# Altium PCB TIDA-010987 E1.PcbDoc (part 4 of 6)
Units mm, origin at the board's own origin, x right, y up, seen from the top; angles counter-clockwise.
Board outline 154.15 x 103.76 mm, 4 copper layers (5V, GND, MidSupply, -5V), stack 1.787 mm thick; 92 components, 52 nets, 1640 pads, 56 vias.
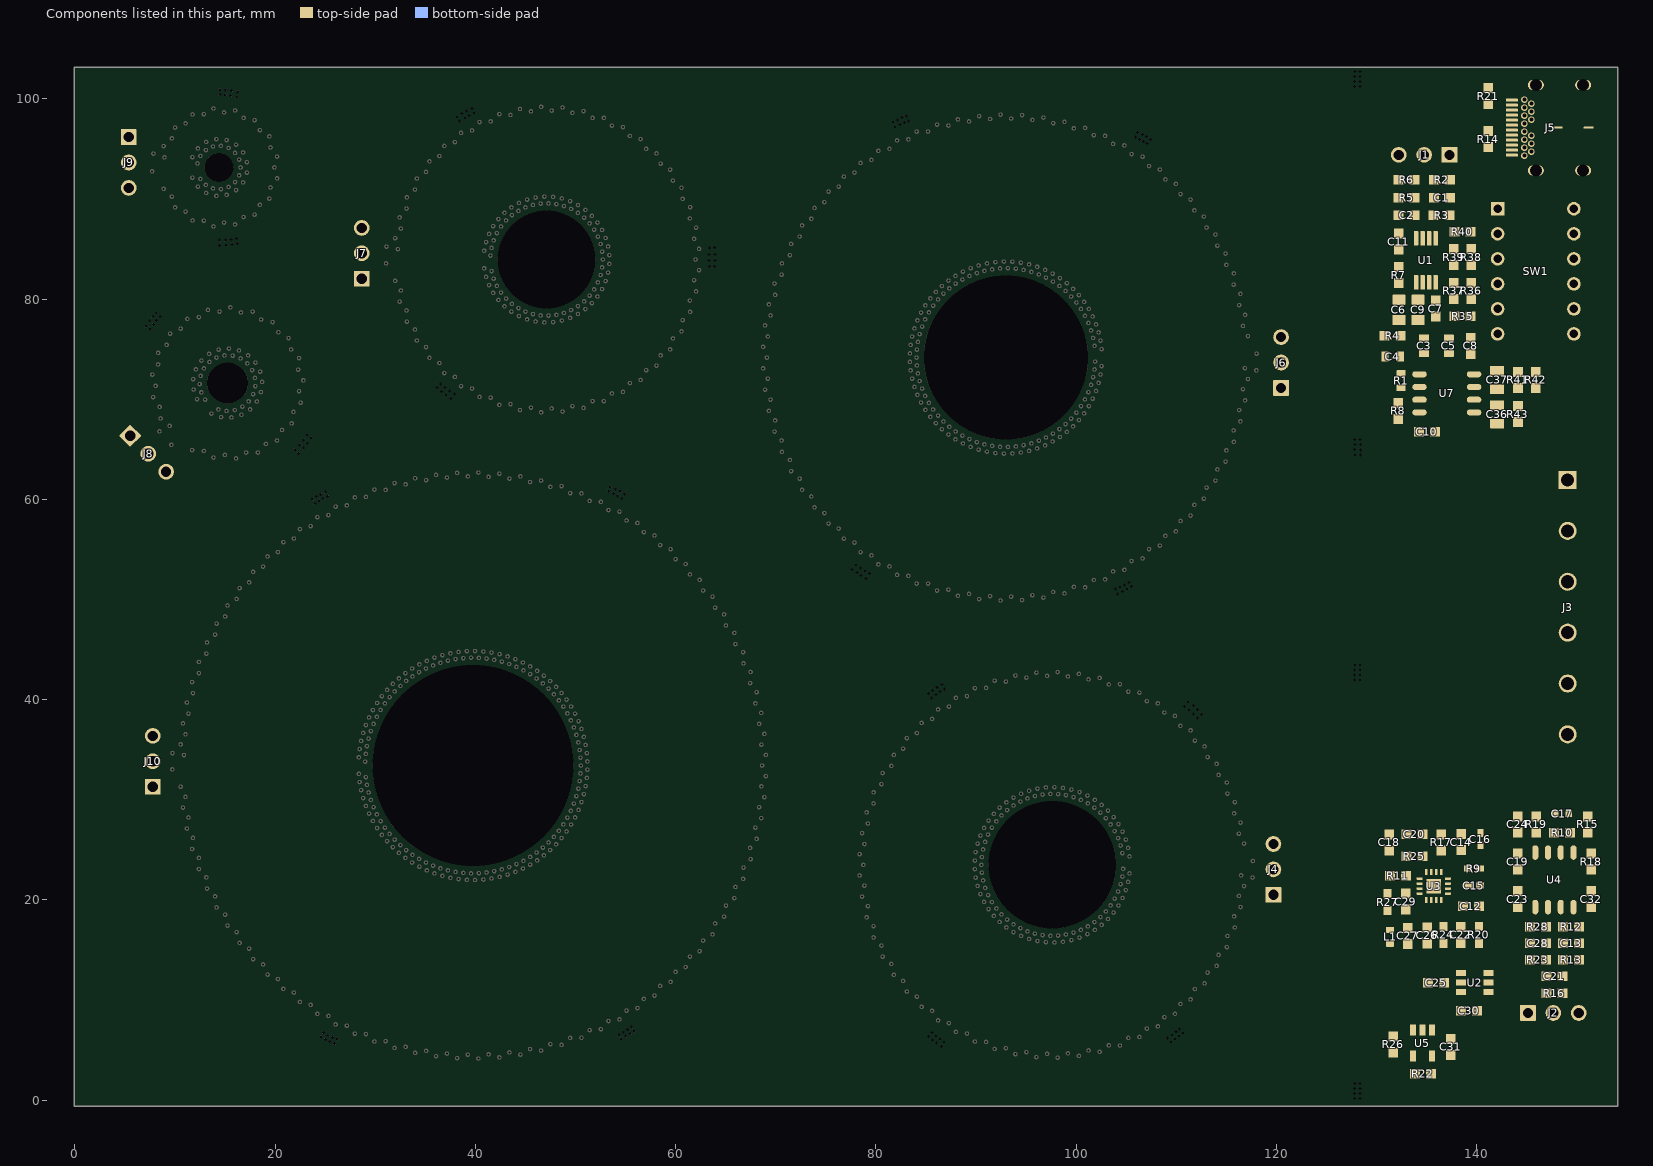
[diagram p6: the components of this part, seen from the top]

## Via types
v1: diameter 0.61, hole 0.203, 5V to -5V, tented both sides, 52 vias
v2: diameter 0.5, hole 0.2, 5V to -5V, tented both sides, 4 vias

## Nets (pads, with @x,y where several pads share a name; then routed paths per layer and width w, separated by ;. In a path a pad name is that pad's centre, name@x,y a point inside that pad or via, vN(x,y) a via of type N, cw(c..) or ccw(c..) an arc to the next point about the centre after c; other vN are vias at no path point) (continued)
copper on no net: (continued)
  5V w0.1: 97.842,31.244 98.148,42.365 ccw(c98.159,42.75) 98.544,42.736 cw(c97.628,23.493) 99.892,42.624 cw(c100.274,42.575) 100.655,42.518 cw(c97.628,23.493) 102.357,42.168 ; 98.213,16.43 99.187,4.677 ; 98.213,30.556 99.187,42.308 ; 98.339,67.001 ccw(c92.996,74.152) 98.657,67.251 cw(c98.95,67.501) 99.231,67.764 ccw(c92.996,74.152) 99.245,67.778 ccw(c99.514,68.053) 99.795,67.79 110.433,57.836 ; 98.339,81.304 ccw(c92.996,74.152) 98.009,81.539 cw(c97.686,81.748) 97.354,81.943 ccw(c92.996,74.152) 97.336,81.953 ccw(c96.996,82.133) 97.169,82.477 103.696,95.501 ; 98.392,66.22 106.428,54.408 ccw(c106.644,54.089) 106.324,53.875 cw(c92.996,74.152) 105.152,53.152 cw(c104.818,52.962) 104.48,52.777 cw(c92.996,74.152) 102.898,52 ; 98.392,82.085 106.644,94.216 ; 98.693,31.173 100.274,42.575 ; 98.95,67.501 108.923,56.359 ; 98.95,80.804 108.923,91.946 ; 98.987,16.537 ccw(c97.628,23.493) 99.373,16.624 cw(c99.744,16.729) 100.108,16.853 ccw(c97.628,23.493) 100.119,16.857 ccw(c100.475,17.002) 100.63,16.65 105.212,6.203 ; 99.072,66.728 108.364,55.374 ; 99.072,81.577 108.12,92.633 ccw(c108.364,92.931) 108.66,92.685 cw(c92.996,74.152) 109.686,91.766 cw(c109.963,91.499) 110.237,91.228 cw(c92.996,74.152) 111.43,89.932 ; 99.514,68.053 ccw(c92.996,74.152) 99.784,68.355 cw(c100.028,68.653) 100.258,68.962 ccw(c92.996,74.152) 100.27,68.978 ccw(c100.486,69.296) 100.809,69.087 113.033,61.161 ; 99.514,80.252 ccw(c92.996,74.152) 99.231,80.541 cw(c98.95,80.804) 98.657,81.054 ccw(c92.996,74.152) 98.642,81.067 ccw(c98.339,81.304) 98.569,81.612 107.288,93.284 ; 99.532,15.976 102.357,4.817 ; 99.532,31.009 102.263,41.795 ccw(c102.357,42.168) 102.73,42.07 cw(c97.628,23.493) 104.021,41.666 cw(c104.383,41.535) 104.742,41.396 cw(c97.628,23.493) 106.327,40.682 ; 99.704,67.294 109.694,57.081 ccw(c109.963,56.806) 109.686,56.539 cw(c92.996,74.152) 108.66,55.62 cw(c108.364,55.374) 108.064,55.133 cw(c92.996,74.152) 106.644,54.089 ; 99.704,81.011 109.963,91.499 ; 99.744,16.729 103.264,5.473 ; 99.744,30.257 103.264,41.512 ; 100.028,68.653 111.807,59.441 ; 100.028,79.652 111.807,88.864 ; 100.274,4.41 ccw(c97.628,23.493) 101.983,4.726 ccw(c102.357,4.817) 102.73,4.915 ccw(c97.628,23.493) 104.021,5.319 cw(c104.383,5.451) 104.248,5.811 100.347,16.231 ; 100.284,67.914 111.43,58.373 ; 100.284,80.391 111.138,89.681 ccw(c111.43,89.932) 111.678,89.637 cw(c92.996,74.152) 112.527,88.552 cw(c112.753,88.241) 112.974,87.926 cw(c92.996,74.152) 113.92,86.44 ; 100.347,30.754 104.383,41.535 ; 100.475,17.002 ccw(c97.628,23.493) 100.833,17.172 cw(c101.172,17.355) 101.5,17.556 ccw(c97.628,23.493) 101.509,17.563 ccw(c101.826,17.782) 102.053,17.472 108.81,8.28 ; 100.475,29.983 ccw(c97.628,23.493) 100.108,30.132 cw(c99.744,30.257) 99.373,30.362 ccw(c97.628,23.493) 99.363,30.364 ccw(c98.987,30.448) 99.061,30.826 101.248,42.022 ; 100.486,69.296 ccw(c92.996,74.152) 100.699,69.641 cw(c100.886,69.977) 101.059,70.321 ccw(c92.996,74.152) 101.068,70.339 ccw(c101.224,70.691) 101.579,70.542 115.008,64.892 ; 100.486,79.009 ccw(c92.996,74.152) 100.258,79.343 cw(c100.028,79.652) 99.784,79.95 ccw(c92.996,74.152) 99.771,79.965 ccw(c99.514,80.252) 99.795,80.515 110.433,90.469 ; 100.807,68.583 112.439,60.288 ccw(c112.753,60.064) 112.527,59.752 cw(c92.996,74.152) 111.678,58.668 cw(c111.43,58.373) 111.177,58.083 cw(c92.996,74.152) 109.963,56.806 ; 100.807,79.722 112.753,88.241 ; 100.886,69.977 114.103,62.983 ; 100.886,78.328 114.103,85.322 ; 101.129,16.574 106.327,6.303 ; 101.129,30.411 106.153,40.338 ccw(c106.327,40.682) 106.669,40.505 cw(c97.628,23.493) 107.841,39.828 cw(c108.165,39.621) 108.485,39.407 cw(c97.628,23.493) 109.875,38.364 ; 101.172,17.355 107.068,7.142 ; 101.172,29.63 107.068,39.843 ; 101.224,70.691 ccw(c92.996,74.152) 101.373,71.068 cw(c101.498,71.432) 101.608,71.801 ccw(c92.996,74.152) 101.613,71.82 ccw(c101.705,72.194) 102.081,72.109 116.294,68.912 ; 101.224,77.614 ccw(c92.996,74.152) 101.059,77.984 cw(c100.886,78.328) 100.699,78.664 ccw(c92.996,74.152) 100.689,78.681 ccw(c100.486,79.009) 100.809,79.218 113.033,87.144 ; 101.269,69.295 113.92,61.865 ; 101.269,79.01 113.588,86.245 ccw(c113.92,86.44) 114.113,86.106 cw(c92.996,74.152) 114.757,84.889 cw(c114.924,84.542) 115.087,84.193 cw(c92.996,74.152) 115.757,82.564 ; 101.498,71.432 115.74,66.874 ; 101.498,76.873 115.74,81.431 ; 101.666,70.045 114.577,63.928 ccw(c114.924,63.763) 114.757,63.416 cw(c92.996,74.152) 114.113,62.199 cw(c113.92,61.865) 113.723,61.535 cw(c92.996,74.152) 112.753,60.064 ; 101.666,78.26 114.924,84.542 ; 101.705,72.194 ccw(c92.996,74.152) 101.785,72.591 cw(c101.844,72.971) 101.887,73.354 ccw(c92.996,74.152) 101.889,73.373 ccw(c101.914,73.758) 102.299,73.741 116.853,73.096 ; 101.705,76.111 ccw(c92.996,74.152) 101.608,76.504 cw(c101.498,76.873) 101.373,77.237 ccw(c92.996,74.152) 101.366,77.256 ccw(c101.224,77.614) 101.579,77.763 115.008,83.413 ; 101.826,17.782 ccw(c97.628,23.493) 102.138,18.025 cw(c102.428,18.278) 102.704,18.547 ccw(c97.628,23.493) 102.712,18.555 ccw(c102.973,18.838) 103.263,18.585 111.866,11.093 ; 101.826,29.203 ccw(c97.628,23.493) 101.5,29.429 cw(c101.172,29.63) 100.833,29.814 ccw(c97.628,23.493) 100.823,29.819 ccw(c100.475,29.983) 100.63,30.335 105.212,40.782 ; 101.844,72.971 116.666,70.992 ; 101.844,75.334 116.666,77.313 ; 101.869,17.001 107.955,7.687 ccw(c108.165,7.365) 107.841,7.157 cw(c97.628,23.493) 106.669,6.481 cw(c106.327,6.303) 105.982,6.133 cw(c97.628,23.493) 104.383,5.451 ; 101.869,29.984 108.165,39.621 ; 101.914,73.758 ccw(c92.996,74.152) 101.923,74.152 118.031,74.152 ; 101.995,70.827 115.757,65.741 ; 101.995,77.478 115.396,82.43 ccw(c115.757,82.564) 115.887,82.201 cw(c92.996,74.152) 116.307,80.89 cw(c116.411,80.519) 116.509,80.147 cw(c92.996,74.152) 116.882,78.425 ; 102.254,71.635 116.04,67.887 ccw(c116.411,67.786) 116.307,67.415 cw(c92.996,74.152) 115.887,66.104 cw(c115.757,65.741) 115.621,65.381 cw(c92.996,74.152) 114.924,63.763 ; 102.254,76.67 116.411,80.519 ; 102.428,18.278 110.415,9.602 ; 102.428,28.707 110.415,37.383 ; 102.44,72.463 116.882,69.88 ; 102.44,75.842 116.503,78.357 ccw(c116.882,78.425) 116.947,78.045 cw(c92.996,74.152) 117.129,76.68 cw(c117.166,76.297) 117.197,75.913 cw(c92.996,74.152) 117.238,75.226 101.914,74.547 ccw(c92.996,74.152) 101.887,74.951 cw(c101.844,75.334) 101.785,75.714 ccw(c92.996,74.152) 101.782,75.734 ccw(c101.705,76.111) 102.081,76.196 116.294,79.393 ; 102.552,73.305 116.783,72.042 ccw(c117.166,72.008) 117.129,71.625 cw(c92.996,74.152) 116.947,70.26 cw(c116.882,69.88) 116.811,69.502 cw(c92.996,74.152) 116.411,67.786 ; 102.552,75 117.166,76.297 ; 102.558,17.507 109.875,8.622 ; 102.558,29.478 109.631,38.066 ccw(c109.875,38.364) 110.17,38.116 cw(c97.628,23.493) 111.166,37.199 cw(c111.437,36.926) 111.703,36.647 cw(c97.628,23.493) 112.831,35.325 ; 102.973,18.838 ccw(c97.628,23.493) 103.224,19.144 cw(c103.452,19.454) 103.663,19.776 ccw(c97.628,23.493) 103.669,19.786 ccw(c103.861,20.12) 104.2,19.936 114.233,14.507 ; 102.973,28.147 ccw(c97.628,23.493) 102.704,28.439 cw(c102.428,28.707) 102.138,28.96 ccw(c97.628,23.493) 102.129,28.967 ccw(c101.826,29.203) 102.053,29.513 108.81,38.705 ; 103.186,18.086 111.161,10.328 ccw(c111.437,10.059) 111.166,9.786 cw(c97.628,23.493) 110.17,8.869 cw(c109.875,8.622) 109.576,8.38 cw(c97.628,23.493) 108.165,7.365 ; 103.186,28.9 111.437,36.926 ; 103.452,19.454 113.143,12.735 ; 103.452,27.531 113.143,34.251 ; 103.747,18.73 112.831,11.66 ; 103.747,28.255 112.527,35.089 ccw(c112.831,35.325) 113.064,35.019 cw(c97.628,23.493) 113.836,33.907 cw(c114.04,33.581) 114.239,33.251 cw(c97.628,23.493) 115.051,31.714 ; 103.861,20.12 ccw(c97.628,23.493) 104.04,20.473 cw(c104.194,20.826) 104.33,21.186 ccw(c97.628,23.493) 104.333,21.197 ccw(c104.448,21.564) 104.818,21.459 115.796,18.355 ; 103.861,26.866 ccw(c97.628,23.493) 103.663,27.209 cw(c103.452,27.531) 103.224,27.841 ccw(c97.628,23.493) 103.218,27.85 ccw(c102.973,28.147) 103.263,28.4 111.866,35.892 ; 104.194,20.826 115.12,16.388 ; 104.194,26.16 115.12,30.597 ; 104.234,19.432 113.712,13.606 ccw(c114.04,13.404) 113.836,13.078 cw(c97.628,23.493) 113.064,11.966 cw(c112.831,11.66) 112.592,11.358 cw(c97.628,23.493) 111.437,10.059 ; 104.234,27.553 114.04,33.581 ; 104.448,21.564 ccw(c97.628,23.493) 104.545,21.948 cw(c104.619,22.326) 104.672,22.707 ccw(c97.628,23.493) 104.673,22.719 ccw(c104.705,23.102) 105.089,23.081 116.48,22.453 ; 104.448,25.421 ccw(c97.628,23.493) 104.33,25.799 cw(c104.194,26.16) 104.04,26.512 ccw(c97.628,23.493) 104.035,26.522 ccw(c103.861,26.866) 104.2,27.049 114.233,32.479 ; 104.619,22.326 116.251,20.385 ; 104.619,24.659 116.251,26.6 ; 104.641,20.183 115.051,15.271 ; 104.641,26.802 114.702,31.55 ccw(c115.051,31.714) 115.211,31.365 cw(c97.628,23.493) 115.721,30.111 cw(c115.849,29.748) 115.971,29.383 cw(c97.628,23.493) 116.427,27.706 ; 104.705,23.102 ccw(c97.628,23.493) 104.715,23.493 117.663,23.493 ; 104.962,20.975 115.485,17.362 ccw(c115.849,17.237) 115.721,16.874 cw(c97.628,23.493) 115.211,15.621 cw(c115.051,15.271) 114.883,14.924 cw(c97.628,23.493) 114.04,13.404 ; 104.962,26.01 115.849,29.748 ; 105.195,21.797 116.427,19.28 ; 105.195,25.188 116.051,27.621 ccw(c116.427,27.706) 116.507,27.329 cw(c97.628,23.493) 116.73,25.994 cw(c116.776,25.612) 116.815,25.229 cw(c97.628,23.493) 116.864,24.554 104.705,23.883 ccw(c97.628,23.493) 104.672,24.278 cw(c104.619,24.659) 104.545,25.037 ccw(c97.628,23.493) 104.543,25.048 ccw(c104.448,25.421) 104.818,25.526 115.796,28.63 ; 105.335,22.64 116.394,21.416 ccw(c116.776,21.373) 116.73,20.991 cw(c97.628,23.493) 116.507,19.656 cw(c116.427,19.28) 116.339,18.905 cw(c97.628,23.493) 115.849,17.237 ; 105.335,24.346 116.776,25.612 ; 116.776,21.373 ccw(c97.628,23.493) 116.875,22.656 117.644,22.614 119.71,25.578 ; 117.166,72.008 ccw(c92.996,74.152) 117.246,73.304 118.016,73.27 120.419,76.243 ; 117.623,22.229 119.71,20.498 ; 117.66,23.878 cw(c97.628,22.987) 117.673,23.493 ; 117.999,72.885 118.052,72.89 120.422,70.906 ; 118.028,74.537 cw(c92.996,73.665) 118.039,74.153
